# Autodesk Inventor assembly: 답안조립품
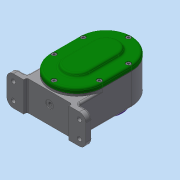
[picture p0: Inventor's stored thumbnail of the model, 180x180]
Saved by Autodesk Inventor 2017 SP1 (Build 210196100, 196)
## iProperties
Part Number: 답안조립품
Material: 일반
Document SubType Name: Assembly
Designer: MRC
Author: MRC
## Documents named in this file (19)
- C:\Users\MRC\Desktop\710609V1013\답안조립품.iam
- C:\Users\MRC\Desktop\710609V1013\본체.ipt
- C:\Users\MRC\Desktop\710609V1013\개스킷 A.ipt
- C:\Users\MRC\Desktop\710609V1013\개스킷 B.ipt
- C:\Users\MRC\Desktop\710609V1013\베어링 6001.ipt
- 베어링 6001.ipt
- C:\Users\MRC\Desktop\710609V1013\베어링 6002.ipt
- 베어링 6002.ipt
- C:\Users\MRC\Desktop\710609V1013\볼트 M4.ipt
- C:\Users\MRC\Desktop\710609V1013\스퍼기어 A.ipt
- C:\Users\MRC\Desktop\710609V1013\스퍼기어 B.ipt
- C:\Users\MRC\Desktop\710609V1013\오일 실 12 22 7.ipt
- C:\Users\MRC\Desktop\710609V1013\축 A.ipt
- C:\Users\MRC\Desktop\710609V1013\축 B.ipt
- C:\Users\MRC\Desktop\710609V1013\칼라.ipt
- C:\Users\MRC\Desktop\710609V1013\커버 A.ipt
- C:\Users\MRC\Desktop\710609V1013\커버 B.ipt
- C:\Users\MRC\Desktop\710609V1013\키 4 x 4 x 12.ipt
- C:\Users\MRC\Desktop\710609V1013\키 5 x 5 x 12.ipt
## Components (2 placed, 2 different names)
1. 개스킷 A:1
2. 개스킷 B:1
